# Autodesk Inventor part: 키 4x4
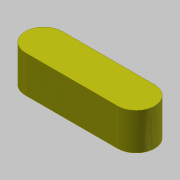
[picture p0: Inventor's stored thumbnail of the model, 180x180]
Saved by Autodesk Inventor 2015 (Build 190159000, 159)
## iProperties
Created: 2018-09
Part Number: 키 4x4
Document SubType Name: Modeling
Density: 1 g/cm^3
Material: 강철, 연강
Appearance: 노란색
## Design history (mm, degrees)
sketch "스케치1"
  geometry: L1 (-5, -2)-(5, -2); L2 (5, 2)-(-5, 2); A1 r 2 centre (5, 0) between (5, -2) and (5, 2); A2 r 2 centre (-5, 0) between (-5, 2) and (-5, -2); 2 further points
  constraints: 4 end point, 4 point on circle, 4 tangent, 2 centre point, 1 horizontal, 1 horizontal alignment, 1 midpoint, 1 parallel, 1 vertical alignment
  dimensions: "d0" = 4 distance between parallel lines of L1 L2; "d1" = 14 dimension on A1 A2
extrude "돌출1" new body sketch "스케치1" stored distance "d2" = 4; taper "d3" = 0 deg
node "솔리드1"
